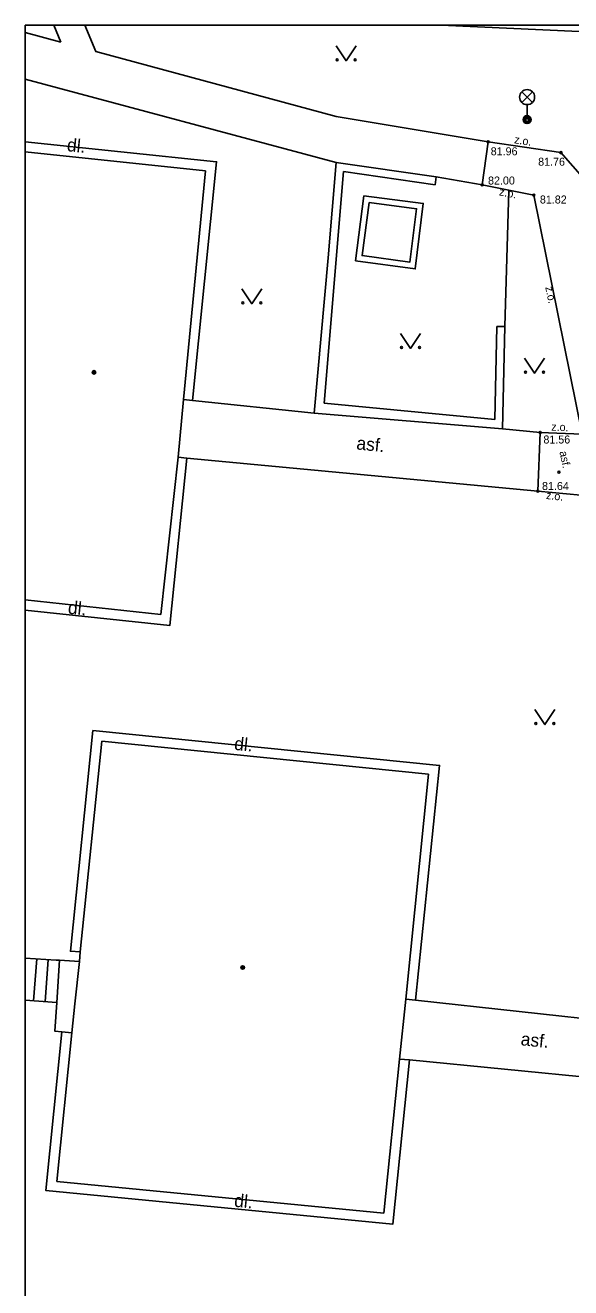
# Model space of a CAD drawing. Extents: x -601752 to -601591, y -1162280 to -1162131.
# Drawn here: x -601752.3 to -601725, y -1162194.2 to -1162131.1 of the extents above; entities that cross this region are included whole.
import ezdxf

# ---------------------------------------------------------------- set-up
doc = ezdxf.new("R2010")
doc.units = 0
for name, color, linetype in [('Level 1', 7, 'Continuous'), ('OKRAJ', 7, 'Continuous'), ('Vrstva 49', 7, 'Continuous'), ('Vrstva 58', 7, 'Continuous'), ('Vrstva 60', 7, 'Continuous'), ('Vrstva 63', 7, 'Continuous'), ('Vrstva 7', 7, 'Continuous')]:
    doc.layers.add(name, color=color, linetype=linetype)

msp = doc.modelspace()

# ---------------------------------------------------------------- linework, layer by layer
at = {"layer": 'Level 1'}
for p, q in [((-601727.485, -1162134.98), (-601726.955, -1162134.45)), ((-601727.485, -1162134.45), (-601726.955, -1162134.98)), ((-601727.22, -1162135.09), (-601727.22, -1162135.84)), ((-601731.76, -1162138.69), (-601729.46, -1162139.1)), ((-601728.45, -1162151.29), (-601726.57, -1162151.47)), ((-601726.69, -1162154.41), (-601744.22, -1162152.75)), ((-601721.197, -1162183.999), (-601733.09, -1162182.83))]:
    msp.add_line(p, q, dxfattribs=at)
for points in [[(-601750.51, -1162131.97), (-601752.281, -1162131.483)], [(-601750.852, -1162131.123), (-601750.51, -1162131.97)], [(-601749.312, -1162131.123), (-601748.76, -1162132.44), (-601736.75, -1162135.68), (-601729.16, -1162136.95)], [(-601707.57, -1162132.22), (-601731.509, -1162131.123)], [(-601736.76, -1162132.15), (-601736.26, -1162132.9), (-601735.76, -1162132.15)], [(-601752.281, -1162133.811), (-601736.75, -1162137.98)], [(-601752.281, -1162136.944), (-601742.73, -1162137.94), (-601743.93, -1162149.88)], [(-601752.281, -1162137.448), (-601743.28, -1162138.39)], [(-601743.28, -1162138.39), (-601744.38, -1162149.83)], [(-601736.75, -1162137.98), (-601737.15, -1162142.74), (-601737.86, -1162150.5)], [(-601737.36, -1162150.01), (-601736.39, -1162138.43)], [(-601736.75, -1162137.98), (-601731.76, -1162138.69)], [(-601736.39, -1162138.43), (-601731.82, -1162139.09)], [(-601731.76, -1162138.69), (-601731.82, -1162139.09)], [(-601735.37, -1162139.64), (-601732.41, -1162140.03), (-601732.81, -1162143.3), (-601735.79, -1162142.89), (-601735.37, -1162139.64)], [(-601728.33, -1162146.17), (-601728.14, -1162139.361)], [(-601735.11, -1162139.98), (-601732.74, -1162140.29), (-601733.07, -1162142.96), (-601735.46, -1162142.63), (-601735.11, -1162139.98)], [(-601741.47, -1162144.29), (-601740.97, -1162145.04), (-601740.47, -1162144.29)], [(-601733.54, -1162146.52), (-601733.04, -1162147.27), (-601732.54, -1162146.52)], [(-601728.73, -1162146.18), (-601728.84, -1162150.82)], [(-601728.73, -1162146.18), (-601728.33, -1162146.17)], [(-601728.33, -1162146.17), (-601728.45, -1162151.29)], [(-601727.35, -1162147.76), (-601726.85, -1162148.51), (-601726.35, -1162147.76)], [(-601744.38, -1162149.83), (-601744.65, -1162152.71)], [(-601744.38, -1162149.83), (-601743.93, -1162149.88)], [(-601743.93, -1162149.88), (-601737.86, -1162150.5)], [(-601728.84, -1162150.82), (-601737.36, -1162150.01)], [(-601737.86, -1162150.5), (-601728.45, -1162151.29)], [(-601744.22, -1162152.75), (-601745.07, -1162161.12), (-601752.281, -1162160.349)], [(-601744.65, -1162152.71), (-601745.51, -1162160.57)], [(-601744.22, -1162152.75), (-601744.65, -1162152.71)], [(-601745.51, -1162160.57), (-601752.281, -1162159.844)], [(-601726.835, -1162165.317), (-601726.335, -1162166.067), (-601725.835, -1162165.317)], [(-601749.54, -1162177.43), (-601750.03, -1162177.4), (-601748.9, -1162166.37), (-601731.59, -1162168.11), (-601732.79, -1162179.84)], [(-601749.54, -1162177.43), (-601748.46, -1162166.9)], [(-601748.46, -1162166.9), (-601732.14, -1162168.55)], [(-601732.14, -1162168.55), (-601733.28, -1162179.79)], [(-601749.58, -1162177.91), (-601749.54, -1162177.43)], [(-601752.281, -1162177.745), (-601750.74, -1162177.84)], [(-601751.71, -1162177.78), (-601751.87, -1162179.87)], [(-601751.29, -1162179.91), (-601751.14, -1162177.82)], [(-601750.74, -1162177.84), (-601750.57, -1162177.85)], [(-601750.57, -1162177.85), (-601750.7, -1162179.95)], [(-601750.57, -1162177.85), (-601749.58, -1162177.91)], [(-601749.8, -1162180.02), (-601749.58, -1162177.91)], [(-601750.7, -1162179.95), (-601752.281, -1162179.836)], [(-601750.45, -1162181.42), (-601750.81, -1162181.39), (-601750.7, -1162179.95)], [(-601749.95, -1162181.47), (-601749.8, -1162180.02)], [(-601733.28, -1162179.79), (-601733.6, -1162182.79)], [(-601732.79, -1162179.84), (-601733.28, -1162179.79)], [(-601722.44, -1162180.98), (-601732.79, -1162179.84)], [(-601733.09, -1162182.83), (-601733.93, -1162191.04), (-601751.25, -1162189.36), (-601750.45, -1162181.42)], [(-601750.71, -1162188.91), (-601749.95, -1162181.47)], [(-601750.45, -1162181.42), (-601749.95, -1162181.47)], [(-601733.6, -1162182.79), (-601734.38, -1162190.49)], [(-601733.09, -1162182.83), (-601733.6, -1162182.79)], [(-601734.38, -1162190.49), (-601750.71, -1162188.91)]]:
    msp.add_lwpolyline(points, dxfattribs=at)
for centre, radius in [((-601736.71, -1162132.85), 0.05), ((-601735.811, -1162132.85), 0.05), ((-601727.22, -1162134.715), 0.375), ((-601727.22, -1162135.84), 0.2), ((-601727.22, -1162135.84), 0.145), ((-601727.22, -1162135.84), 0.0876), ((-601741.42, -1162144.99), 0.05), ((-601740.521, -1162144.99), 0.05), ((-601733.49, -1162147.22), 0.05), ((-601732.591, -1162147.22), 0.05), ((-601748.851, -1162148.468), 0.09), ((-601748.851, -1162148.468), 0.0398), ((-601727.3, -1162148.46), 0.05), ((-601726.401, -1162148.46), 0.05), ((-601726.785, -1162166.017), 0.05), ((-601725.885, -1162166.017), 0.05), ((-601741.42, -1162178.21), 0.09), ((-601741.42, -1162178.21), 0.0398)]:
    msp.add_circle(centre, radius, dxfattribs=at)
at = {"layer": 'OKRAJ'}
for p, q in [((-601738.967, -1162131.123), (-601752.281, -1162131.123)), ((-601752.281, -1162131.123), (-601752.281, -1162205.373)), ((-601686.467, -1162131.123), (-601738.967, -1162131.123))]:
    msp.add_line(p, q, dxfattribs=at)
at = {"layer": 'Vrstva 60'}
for centre in [(-601729.16, -1162136.95), (-601725.53, -1162137.49), (-601729.46, -1162139.1), (-601726.88, -1162139.61), (-601726.57, -1162151.47), (-601725.63, -1162153.46), (-601726.69, -1162154.41)]:
    msp.add_circle(centre, 0.05, dxfattribs=at)
at = {"layer": 'Vrstva 63'}
for points in [[(-601729.16, -1162136.95), (-601729.46, -1162139.1)], [(-601726.57, -1162151.47), (-601726.69, -1162154.41)]]:
    msp.add_lwpolyline(points, dxfattribs=at)
at = {"layer": 'Vrstva 7'}
for points in [[(-601729.16, -1162136.95), (-601729.46, -1162139.1)], [(-601693.93, -1162141.67), (-601694.74, -1162141.53), (-601700.24, -1162140.55), (-601712.7, -1162143.08), (-601719.43, -1162144.44), (-601725.53, -1162137.49), (-601729.16, -1162136.95)], [(-601729.46, -1162139.1), (-601726.88, -1162139.61), (-601724.47, -1162151.55), (-601726.57, -1162151.47)], [(-601726.69, -1162154.41), (-601723.82, -1162154.67), (-601722.32, -1162161.86), (-601721.37, -1162166.31)]]:
    msp.add_lwpolyline(points, dxfattribs=at)

# ---------------------------------------------------------------- texts
at = {"layer": 'Level 1'}
for s, p in [('dl.', (-601750.22, -1162137.41)), ('asf.', (-601735.766, -1162152.315)), ('dl.', (-601750.172, -1162160.525)), ('dl.', (-601741.87, -1162167.33)), ('asf.', (-601727.561, -1162182.092)), ('dl.', (-601741.87, -1162190.16))]:
    msp.add_text(s, height=0.65, rotation=354.23, dxfattribs=at).set_placement(p)
at = {"layer": 'Vrstva 49'}
for s, rotation, p in [('z.o.', 351.28295, (-601727.886, -1162137.018)), ('z.o.', 349.40065, (-601728.638, -1162139.621)), ('z.o.', 281.89386, (-601726.317, -1162144.214)), ('z.o.', 357.80844, (-601726.019, -1162151.379)), ('asf.', 281.62711, (-601725.607, -1162152.439)), ('z.o.', 353.91266, (-601726.289, -1162154.794))]:
    msp.add_text(s, height=0.4, rotation=rotation, dxfattribs=at).set_placement(p)
at = {"layer": 'Vrstva 58'}
for s, p in [('81.96', (-601729.038, -1162137.621)), ('81.76', (-601726.669, -1162138.142)), ('82.00', (-601729.172, -1162139.082)), ('81.82', (-601726.582, -1162140.031)), ('81.56', (-601726.407, -1162152.024)), ('81.64', (-601726.476, -1162154.347))]:
    msp.add_text(s, height=0.4, dxfattribs=at).set_placement(p)

doc.saveas('drawing.dxf')
